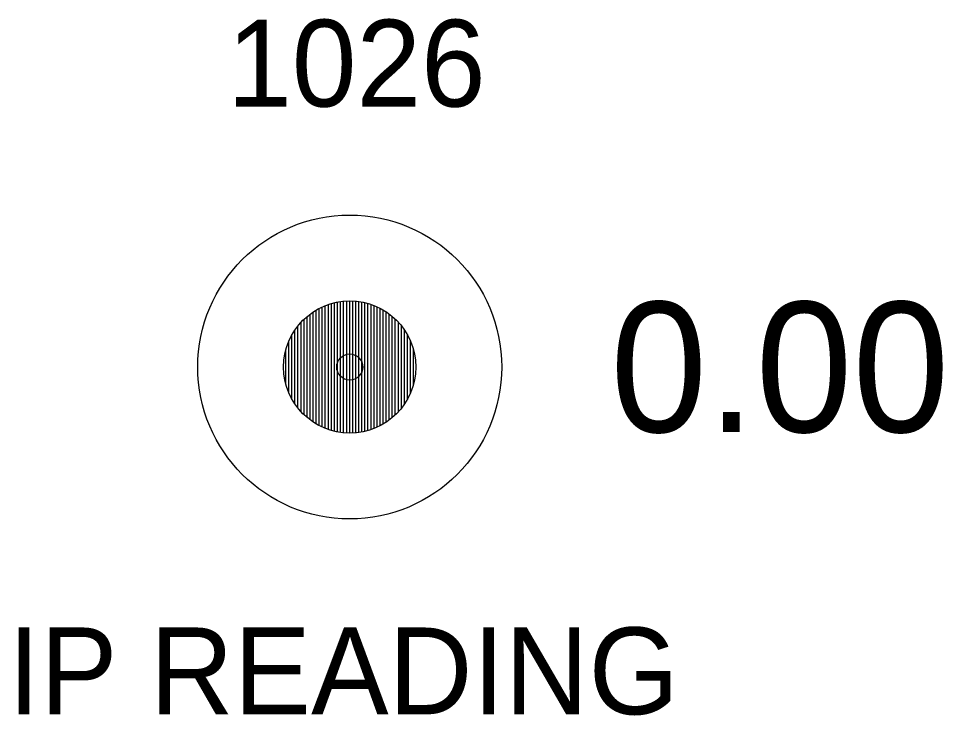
# Model space of a CAD drawing. Extents: x 1448136 to 1453623, y 1125056 to 1128842.
# Drawn here: x 1453034.77 to 1453045.41, y 1125268.22 to 1125276.25 of the extents above; entities that cross this region are included whole.
import ezdxf

# ---------------------------------------------------------------- set-up
doc = ezdxf.new("R2010")
doc.units = 0
for name, color, linetype in [('RD_EX_DV_Prop_txCode', 7, 'Continuous'), ('RD_EX_DV_PropPin', 7, 'Continuous'), ('RD_EX_TX_DV_Prop_ELEV', 7, 'Continuous'), ('RD_SMD_Locator', 7, 'Continuous')]:
    doc.layers.add(name, color=color, linetype=linetype)

msp = doc.modelspace()

# ---------------------------------------------------------------- linework, layer by layer
at = {"layer": 'RD_EX_DV_PropPin'}
for p, q in [((1453038.37, 1125271.506), (1453038.37, 1125272.969)), ((1453038.406, 1125271.497), (1453038.406, 1125272.978)), ((1453038.441, 1125271.49), (1453038.441, 1125272.986)), ((1453038.476, 1125271.484), (1453038.476, 1125272.992)), ((1453038.511, 1125271.48), (1453038.511, 1125272.996)), ((1453038.546, 1125271.478), (1453038.546, 1125272.998)), ((1453038.581, 1125271.477), (1453038.581, 1125272.999)), ((1453038.616, 1125271.478), (1453038.616, 1125272.998)), ((1453038.651, 1125271.48), (1453038.651, 1125272.996)), ((1453038.686, 1125271.484), (1453038.686, 1125272.992)), ((1453038.721, 1125271.49), (1453038.721, 1125272.986)), ((1453038.756, 1125271.497), (1453038.756, 1125272.978)), ((1453038.791, 1125271.506), (1453038.791, 1125272.969)), ((1453038.16, 1125271.603), (1453038.16, 1125272.872)), ((1453038.195, 1125271.581), (1453038.195, 1125272.894)), ((1453038.23, 1125271.562), (1453038.23, 1125272.913)), ((1453038.265, 1125271.545), (1453038.265, 1125272.931)), ((1453038.3, 1125271.53), (1453038.3, 1125272.945)), ((1453038.335, 1125271.517), (1453038.335, 1125272.958)), ((1453038.826, 1125271.517), (1453038.826, 1125272.958)), ((1453038.861, 1125271.53), (1453038.861, 1125272.945)), ((1453038.896, 1125271.545), (1453038.896, 1125272.931)), ((1453038.931, 1125271.562), (1453038.931, 1125272.913)), ((1453038.966, 1125271.581), (1453038.966, 1125272.894)), ((1453039.001, 1125271.603), (1453039.001, 1125272.872)), ((1453038.02, 1125271.723), (1453038.02, 1125272.753)), ((1453038.055, 1125271.687), (1453038.055, 1125272.789)), ((1453038.09, 1125271.656), (1453038.09, 1125272.82)), ((1453038.125, 1125271.628), (1453038.125, 1125272.848)), ((1453039.036, 1125271.628), (1453039.036, 1125272.848)), ((1453039.071, 1125271.656), (1453039.071, 1125272.82)), ((1453039.106, 1125271.687), (1453039.106, 1125272.789)), ((1453039.141, 1125271.723), (1453039.141, 1125272.753)), ((1453037.95, 1125271.811), (1453037.95, 1125272.664)), ((1453037.985, 1125271.764), (1453037.985, 1125272.712)), ((1453039.176, 1125271.764), (1453039.176, 1125272.712)), ((1453039.211, 1125271.811), (1453039.211, 1125272.664)), ((1453037.915, 1125271.868), (1453037.915, 1125272.607)), ((1453039.246, 1125271.868), (1453039.246, 1125272.607)), ((1453037.845, 1125272.042), (1453037.845, 1125272.434)), ((1453037.88, 1125271.94), (1453037.88, 1125272.536)), ((1453039.281, 1125271.94), (1453039.281, 1125272.536)), ((1453039.316, 1125272.042), (1453039.316, 1125272.434))]:
    msp.add_line(p, q, dxfattribs=at)
for radius in [1.75, 0.761]:
    msp.add_circle((1453038.581, 1125272.238), radius, dxfattribs=at)
at = {"layer": 'RD_SMD_Locator'}
msp.add_circle((1453038.581, 1125272.238), 0.15, dxfattribs=at)

# ---------------------------------------------------------------- texts
at = {"layer": 'RD_EX_DV_Prop_txCode'}
for s, p in [('1026', (1453037.171, 1125275.238)), ('IP READING', (1453034.644, 1125268.238))]:
    msp.add_text(s, height=1, dxfattribs=at).set_placement(p)
at = {"layer": 'RD_EX_TX_DV_Prop_ELEV'}
msp.add_text('0.00', height=1.5, dxfattribs=at).set_placement((1453041.581, 1125271.488))

doc.saveas('drawing.dxf')
